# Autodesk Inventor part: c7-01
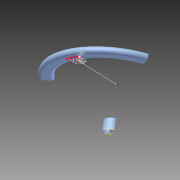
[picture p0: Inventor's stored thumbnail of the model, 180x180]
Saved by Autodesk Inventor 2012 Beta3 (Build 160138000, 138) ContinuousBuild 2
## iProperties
Created: 2010-12
Part Number: c7-01
Document SubType Name: Modeling
Designer: Thom Tremblay
Density: 1 g/cm^3
Material: Default
Author: Thom Tremblay
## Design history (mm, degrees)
sketch "Sketch2"
  geometry: L1 (0, 0)-(-11.43, 0); L2 (-11.43, 0)-(-11.43, 16.51); L3 (-11.43, 16.51)-(0, 16.51); L4 (0, 16.51)-(0, 0); L5 (-96.52, 66.04)-(-86.36, 66.04); L6 (-86.36, 76.2)-(-96.52, 76.2); L7 (-95.25, 74.93)-(-87.63, 74.93); L8 (-96.52, 76.2)-(-95.25, 74.93); L9 (-86.36, 76.2)-(-87.63, 74.93); A1 r 5.08 centre (-86.36, 71.12) between (-86.36, 66.04) and (-86.36, 76.2); A2 r 5.08 centre (-96.52, 71.12) between (-96.52, 76.2) and (-96.52, 66.04)
  constraints: 18 end point, 4 parallel, 4 point on circle, 4 tangent, 2 centre point, 2 horizontal, 2 perpendicular
  dimensions: "d6" = 16.51 distance of L1.end L2.end; "d7" = 22.86 diameter of L2 L4; "d10" = 5.08 radius of A1; "d11" = 20.32 dimension on A2 A1; "d12" = 3.81 distance from line of A1.centre L7; "d13" = 7.62 distance of L7.start L7.end; "d14" = 76.2 distance from line of L6.end L1; "d15" = 203.2 dimension on A2 L4
revolve "Revolution1" sketch "Sketch2" stored, may be unused: angle "d16" = 120 deg
sketch "Loft Sketch 1"
  geometry: L1 (-91.007, -8.89)-(-91.007, 8.89); A1 r 88.9 centre (0, 0) between (-88.479, 8.643) and (-88.479, -8.643); A2 r 93.98 centre (0, 0) between (-93.535, 9.137) and (-93.535, -9.137); A3 r 2.54 centre (-91.007, -8.89) between (-93.535, -9.137) and (-88.479, -8.643); A4 r 2.54 centre (-91.007, 8.89) between (-88.479, 8.643) and (-93.535, 9.137); 2 further points
  constraints: 8 point on circle, 4 centre point, 4 tangent, 2 end point, 1 coincident, 1 midpoint, 1 vertical
  dimensions: "d17" = 17.78 distance of L1.start L1.end; "d18" = 88.9 radius of A1; "d19" = 5.08 diameter of A4
sketch "Loft Sketch 2"
  geometry: C1 r 3.81 at (0, 7.62); 1 further point
  constraints: 1 centre point, 1 vertical alignment
  dimensions: "d63" = 7.62 diameter of C1; "d64" = 7.62 distance of point (0, 0) C1.centre
body "Solid1"
